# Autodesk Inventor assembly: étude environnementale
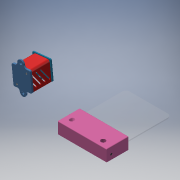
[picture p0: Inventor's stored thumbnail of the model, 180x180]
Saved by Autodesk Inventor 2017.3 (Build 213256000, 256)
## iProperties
Part Number: étude environnementale
Material: Générique
Document SubType Name: Assembly
Designer: ficho
Author: ficho
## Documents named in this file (9)
- C:\Users\ficho\Desktop\réforme\activité rentrée\étude environnementale.iam
- C:\Users\ficho\Desktop\réforme\activité rentrée\base inférieure version 2.ipt
- C:\Users\ficho\Desktop\réforme\activité rentrée\bouchon.ipt
- C:\Users\ficho\Desktop\réforme\activité rentrée\raidisseur.ipt
- C:\Users\ficho\Desktop\réforme\activité rentrée\capot.ipt
- C:\Users\ficho\Desktop\réforme\activité rentrée\capot avant.ipt
- C:\Users\ficho\OneDrive\Documents\Inventor\Content Center Files\R2017\fr-FR\ISO 7046-1 H(1)\ISO 7046-1 - M2 x 3 - 4.8 - H - ISO.ipt
- C:\Users\ficho\OneDrive\Documents\Inventor\Content Center Files\R2017\fr-FR\ISO 4762(2)\ISO 4762 - M3 x 5ISO.ipt
- C:\Users\ficho\Desktop\réforme\activité rentrée\bloc porte lumineux version 2.iam
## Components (11 placed, 8 different names)
1. base inférieure version 2:1 — Placage:2, Affleurement:4, Placage:5, Placage:6, Placage:7, Placage:8, Placage:14, Placage:16
2. bouchon:1 — Placage:2, Affleurement:4, Logement:1, Logement:2, Placage:9
3. raidisseur:1 — Logement:1
4. raidisseur:2 — Logement:2
5. capot:1 — Placage:5, Placage:6, Placage:7, Placage:10
6. capot avant:1 — Placage:8, Placage:9, Placage:10
7. ISO 7046-1 H M2 x 3 - 4.8 - H:1
8. ISO 7046-1 H M2 x 3 - 4.8 - H:2
9. ISO 4762 M3 x 5:1 — Placage:14
10. ISO 4762 M3 x 5:2 — Placage:16
11. bloc porte lumineux version 2:1 [sub-assembly]
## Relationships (12: Mate 9, Insert 2, Flush 1)
- Placage:2 [Mate]: base inférieure version 2:1 ↔ bouchon:1
- Affleurement:4 [Flush]: base inférieure version 2:1 ↔ bouchon:1
- Logement:1 [Insert]: bouchon:1 ↔ raidisseur:1
- Logement:2 [Insert]: bouchon:1 ↔ raidisseur:2
- Placage:5 [Mate]: base inférieure version 2:1 ↔ capot:1
- Placage:6 [Mate]: base inférieure version 2:1 ↔ capot:1
- Placage:7 [Mate]: base inférieure version 2:1 ↔ capot:1
- Placage:8 [Mate]: base inférieure version 2:1 ↔ capot avant:1
- Placage:9 [Mate]: bouchon:1 ↔ capot avant:1
- Placage:10 [Mate]: capot:1 ↔ capot avant:1
- Placage:14 [Mate]: base inférieure version 2:1 ↔ ISO 4762 M3 x 5:1
- Placage:16 [Mate]: base inférieure version 2:1 ↔ ISO 4762 M3 x 5:2
